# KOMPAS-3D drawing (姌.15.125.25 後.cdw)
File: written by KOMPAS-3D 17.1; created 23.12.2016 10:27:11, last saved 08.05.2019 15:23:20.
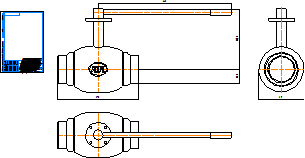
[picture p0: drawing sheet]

Sheet 1: A4, portrait

Title block, sheet 1: name: КШ.15.125.25 сс; material: Внимание! Данный продукт является объектом авторского права ООО «Торговый Дом АДЛ». / Запрещается изменение, копирование, распространение / (в том числе путем копирования на другие сайты и ресурсы в Интернете) / или любое иное использование информации и объектов без предварительного / согласия правообладателя (ООО «Торговый Дом АДЛ»).; sheets: 1; organisation: ООО "Торговый дом АДЛ"; sheet format: A4; stored path: C:\Users\tra\Desktop\2д чертежи\Шаровые краны БИВАЛ\КШ_Бивал_серия_14_15\KOMPAS_2D\КШ.15.125.25 сс.cdw

Views: Вид 1, Проекционный вид 2, Проекционный вид 3
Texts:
  Klimkovich
  ADL
Dimensions and other numbers on the sheet: 390; 645; 291,6; 66,5; 219; 1:1; 1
